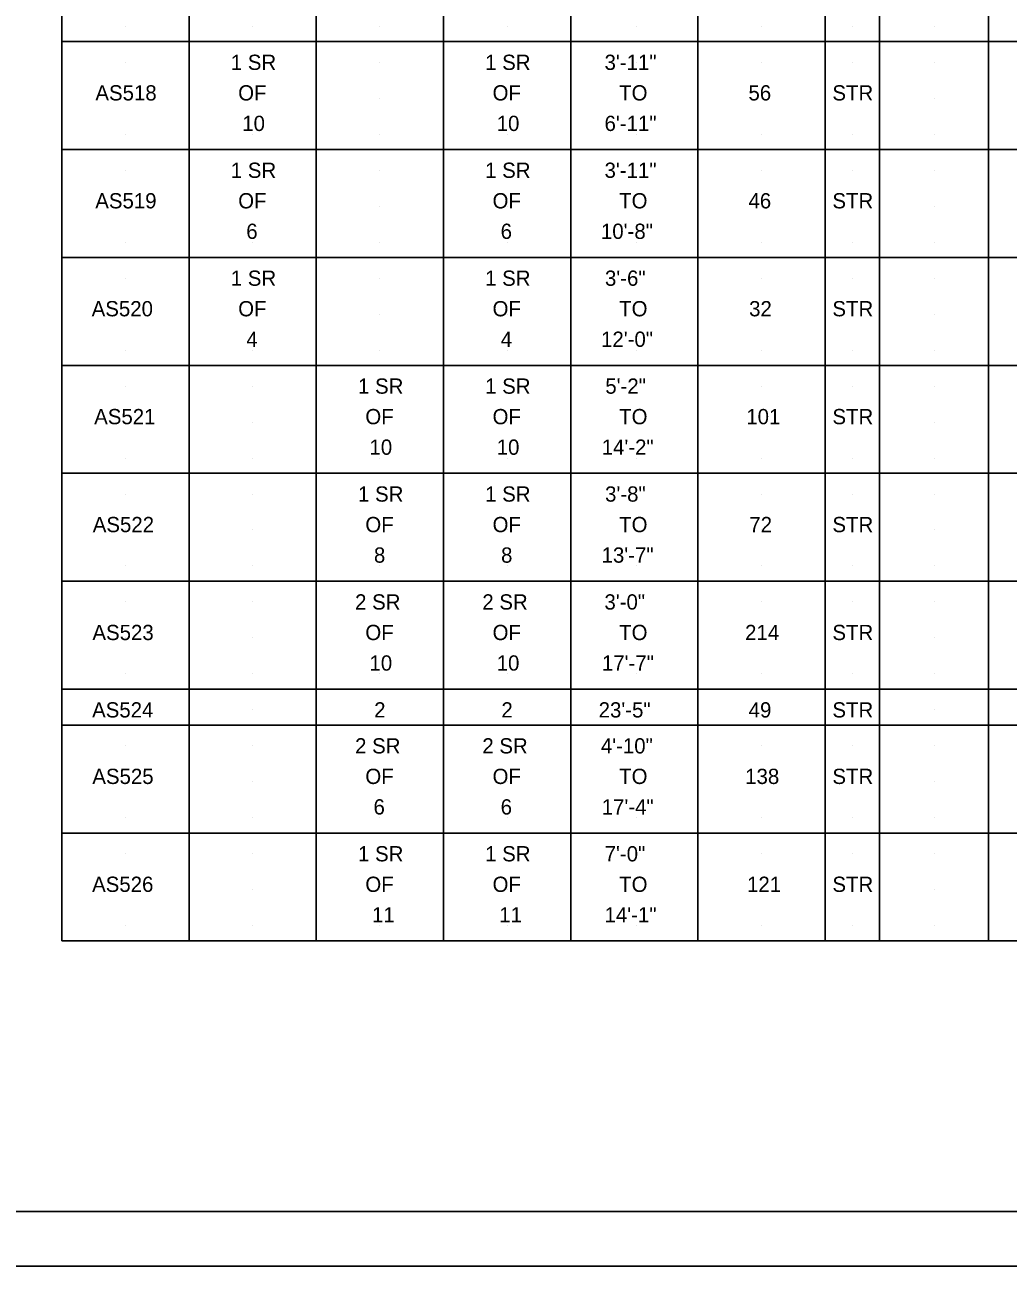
# Model space of a CAD drawing. Extents: x -31.1 to 2.9, y 8.5 to 31.4.
# Drawn here: x -15.02 to -6, y 8.48 to 19.87 of the extents above; entities that cross this region are included whole.
import ezdxf

# ---------------------------------------------------------------- set-up
doc = ezdxf.new("R2010")
doc.units = 0
for name, color, linetype in [('BR_P_Gen_Text', 7, 'Continuous'), ('Default', 7, 'Continuous'), ('SC_Scratch1', 7, 'Continuous')]:
    doc.layers.add(name, color=color, linetype=linetype)

msp = doc.modelspace()

# ---------------------------------------------------------------- linework, layer by layer
at = {"layer": 'BR_P_Gen_Text'}
for p, q in [((-13.511, 28.577), (-13.511, 11.467)), ((-12.345, 28.577), (-12.345, 11.467)), ((-11.178, 28.577), (-11.178, 11.467)), ((-10.011, 28.577), (-10.011, 11.467)), ((-8.845, 28.577), (-8.845, 11.467)), ((-7.678, 28.577), (-7.678, 11.467)), ((-7.178, 28.577), (-7.178, 11.467)), ((-6.178, 28.577), (-6.178, 11.467)), ((-14.678, 19.717), (-0.178, 19.717)), ((-14.678, 18.727), (-0.178, 18.727)), ((-14.678, 17.737), (-0.178, 17.737)), ((-14.678, 16.747), (-0.178, 16.747)), ((-14.678, 15.757), (-0.178, 15.757)), ((-14.678, 14.767), (-0.178, 14.767)), ((-14.678, 13.777), (-0.178, 13.777)), ((-14.678, 13.447), (-0.178, 13.447)), ((-14.678, 12.457), (-0.178, 12.457)), ((-0.178, 11.467), (-14.678, 11.467)), ((-14.678, 11.467), (-0.178, 11.467)), ((-14.678, 11.467), (-0.178, 11.467))]:
    msp.add_line(p, q, dxfattribs=at)
for points in [[(-31.128, 30.484), (2.872, 30.484), (2.872, 8.484), (-31.128, 8.484)], [(-29.128, 29.984), (1.372, 29.984), (1.372, 8.984), (-29.128, 8.984)]]:
    msp.add_lwpolyline(points, close=True, dxfattribs=at)
at = {"layer": 'Default'}
msp.add_line((-14.678, 29.627), (-14.678, 11.467), dxfattribs=at)
at = {"layer": 'SC_Scratch1'}
for p, q in [((-14.095, 19.857), (-14.095, 19.857)), ((-12.928, 19.857), (-12.928, 19.857)), ((-11.761, 19.857), (-11.761, 19.857)), ((-10.595, 19.857), (-10.595, 19.857)), ((-9.407, 19.857), (-9.407, 19.857)), ((-9.407, 19.857), (-9.407, 19.857)), ((-8.261, 19.857), (-8.261, 19.857)), ((-8.261, 19.857), (-8.261, 19.857)), ((-7.428, 19.857), (-7.428, 19.857)), ((-7.428, 19.857), (-7.428, 19.857)), ((-6.678, 19.857), (-6.678, 19.857)), ((-6.678, 19.857), (-6.678, 19.857)), ((-14.095, 19.527), (-14.095, 19.527)), ((-12.928, 19.527), (-12.928, 19.527)), ((-11.761, 19.527), (-11.761, 19.527)), ((-10.595, 19.527), (-10.595, 19.527)), ((-9.407, 19.527), (-9.407, 19.527)), ((-9.407, 19.527), (-9.407, 19.527)), ((-8.261, 19.527), (-8.261, 19.527)), ((-8.261, 19.527), (-8.261, 19.527)), ((-7.428, 19.527), (-7.428, 19.527)), ((-7.428, 19.527), (-7.428, 19.527)), ((-6.678, 19.527), (-6.678, 19.527)), ((-6.678, 19.527), (-6.678, 19.527)), ((-14.095, 19.197), (-14.095, 19.197)), ((-12.928, 19.197), (-12.928, 19.197)), ((-11.761, 19.197), (-11.761, 19.197)), ((-10.595, 19.197), (-10.595, 19.197)), ((-9.407, 19.197), (-9.407, 19.197)), ((-9.407, 19.197), (-9.407, 19.197)), ((-8.261, 19.197), (-8.261, 19.197)), ((-8.261, 19.197), (-8.261, 19.197)), ((-7.428, 19.197), (-7.428, 19.197)), ((-7.428, 19.197), (-7.428, 19.197)), ((-6.678, 19.197), (-6.678, 19.197)), ((-6.678, 19.197), (-6.678, 19.197)), ((-14.095, 18.867), (-14.095, 18.867)), ((-12.928, 18.867), (-12.928, 18.867)), ((-11.761, 18.867), (-11.761, 18.867)), ((-10.595, 18.867), (-10.595, 18.867)), ((-9.407, 18.867), (-9.407, 18.867)), ((-9.407, 18.867), (-9.407, 18.867)), ((-8.261, 18.867), (-8.261, 18.867)), ((-8.261, 18.867), (-8.261, 18.867)), ((-7.428, 18.867), (-7.428, 18.867)), ((-7.428, 18.867), (-7.428, 18.867)), ((-6.678, 18.867), (-6.678, 18.867)), ((-6.678, 18.867), (-6.678, 18.867)), ((-14.095, 18.537), (-14.095, 18.537)), ((-12.928, 18.537), (-12.928, 18.537)), ((-11.761, 18.537), (-11.761, 18.537)), ((-10.595, 18.537), (-10.595, 18.537)), ((-9.407, 18.537), (-9.407, 18.537)), ((-9.407, 18.537), (-9.407, 18.537)), ((-8.261, 18.537), (-8.261, 18.537)), ((-8.261, 18.537), (-8.261, 18.537)), ((-7.428, 18.537), (-7.428, 18.537)), ((-7.428, 18.537), (-7.428, 18.537)), ((-6.678, 18.537), (-6.678, 18.537)), ((-6.678, 18.537), (-6.678, 18.537)), ((-14.095, 18.207), (-14.095, 18.207)), ((-12.928, 18.207), (-12.928, 18.207)), ((-11.761, 18.207), (-11.761, 18.207)), ((-10.595, 18.207), (-10.595, 18.207)), ((-9.407, 18.207), (-9.407, 18.207)), ((-9.407, 18.207), (-9.407, 18.207)), ((-8.261, 18.207), (-8.261, 18.207)), ((-8.261, 18.207), (-8.261, 18.207)), ((-7.428, 18.207), (-7.428, 18.207)), ((-7.428, 18.207), (-7.428, 18.207)), ((-6.678, 18.207), (-6.678, 18.207)), ((-6.678, 18.207), (-6.678, 18.207)), ((-14.095, 17.877), (-14.095, 17.877)), ((-12.928, 17.877), (-12.928, 17.877)), ((-11.761, 17.877), (-11.761, 17.877)), ((-10.595, 17.877), (-10.595, 17.877)), ((-9.407, 17.877), (-9.407, 17.877)), ((-9.407, 17.877), (-9.407, 17.877)), ((-8.261, 17.877), (-8.261, 17.877)), ((-8.261, 17.877), (-8.261, 17.877)), ((-7.428, 17.877), (-7.428, 17.877)), ((-7.428, 17.877), (-7.428, 17.877)), ((-6.678, 17.877), (-6.678, 17.877)), ((-6.678, 17.877), (-6.678, 17.877)), ((-14.095, 17.547), (-14.095, 17.547)), ((-12.928, 17.547), (-12.928, 17.547)), ((-11.761, 17.547), (-11.761, 17.547)), ((-10.595, 17.547), (-10.595, 17.547)), ((-9.407, 17.547), (-9.407, 17.547)), ((-9.407, 17.547), (-9.407, 17.547)), ((-8.261, 17.547), (-8.261, 17.547)), ((-8.261, 17.547), (-8.261, 17.547)), ((-7.428, 17.547), (-7.428, 17.547)), ((-7.428, 17.547), (-7.428, 17.547)), ((-6.678, 17.547), (-6.678, 17.547)), ((-6.678, 17.547), (-6.678, 17.547)), ((-14.095, 17.217), (-14.095, 17.217)), ((-12.928, 17.217), (-12.928, 17.217)), ((-11.761, 17.217), (-11.761, 17.217)), ((-10.595, 17.217), (-10.595, 17.217)), ((-9.407, 17.217), (-9.407, 17.217)), ((-9.407, 17.217), (-9.407, 17.217)), ((-8.261, 17.217), (-8.261, 17.217)), ((-8.261, 17.217), (-8.261, 17.217)), ((-7.428, 17.217), (-7.428, 17.217)), ((-7.428, 17.217), (-7.428, 17.217)), ((-6.678, 17.217), (-6.678, 17.217)), ((-6.678, 17.217), (-6.678, 17.217)), ((-14.095, 16.887), (-14.095, 16.887)), ((-12.928, 16.887), (-12.928, 16.887)), ((-11.761, 16.887), (-11.761, 16.887)), ((-10.595, 16.887), (-10.595, 16.887)), ((-9.407, 16.887), (-9.407, 16.887)), ((-9.407, 16.887), (-9.407, 16.887)), ((-8.261, 16.887), (-8.261, 16.887)), ((-8.261, 16.887), (-8.261, 16.887)), ((-7.428, 16.887), (-7.428, 16.887)), ((-7.428, 16.887), (-7.428, 16.887)), ((-6.678, 16.887), (-6.678, 16.887)), ((-6.678, 16.887), (-6.678, 16.887)), ((-14.095, 16.557), (-14.095, 16.557)), ((-12.928, 16.557), (-12.928, 16.557)), ((-11.761, 16.557), (-11.761, 16.557)), ((-10.595, 16.557), (-10.595, 16.557)), ((-9.407, 16.557), (-9.407, 16.557)), ((-9.407, 16.557), (-9.407, 16.557)), ((-8.261, 16.557), (-8.261, 16.557)), ((-8.261, 16.557), (-8.261, 16.557)), ((-7.428, 16.557), (-7.428, 16.557)), ((-7.428, 16.557), (-7.428, 16.557)), ((-6.678, 16.557), (-6.678, 16.557)), ((-6.678, 16.557), (-6.678, 16.557)), ((-14.095, 16.227), (-14.095, 16.227)), ((-12.928, 16.227), (-12.928, 16.227)), ((-11.761, 16.227), (-11.761, 16.227)), ((-10.595, 16.227), (-10.595, 16.227)), ((-9.407, 16.227), (-9.407, 16.227)), ((-9.407, 16.227), (-9.407, 16.227)), ((-8.261, 16.227), (-8.261, 16.227)), ((-8.261, 16.227), (-8.261, 16.227)), ((-7.428, 16.227), (-7.428, 16.227)), ((-7.428, 16.227), (-7.428, 16.227)), ((-6.678, 16.227), (-6.678, 16.227)), ((-6.678, 16.227), (-6.678, 16.227)), ((-14.095, 15.897), (-14.095, 15.897)), ((-12.928, 15.897), (-12.928, 15.897)), ((-11.761, 15.897), (-11.761, 15.897)), ((-10.595, 15.897), (-10.595, 15.897)), ((-9.407, 15.897), (-9.407, 15.897)), ((-9.407, 15.897), (-9.407, 15.897)), ((-8.261, 15.897), (-8.261, 15.897)), ((-8.261, 15.897), (-8.261, 15.897)), ((-7.428, 15.897), (-7.428, 15.897)), ((-7.428, 15.897), (-7.428, 15.897)), ((-6.678, 15.897), (-6.678, 15.897)), ((-6.678, 15.897), (-6.678, 15.897)), ((-14.095, 15.567), (-14.095, 15.567)), ((-12.928, 15.567), (-12.928, 15.567)), ((-11.761, 15.567), (-11.761, 15.567)), ((-10.595, 15.567), (-10.595, 15.567)), ((-9.407, 15.567), (-9.407, 15.567)), ((-9.407, 15.567), (-9.407, 15.567)), ((-8.261, 15.567), (-8.261, 15.567)), ((-8.261, 15.567), (-8.261, 15.567)), ((-7.428, 15.567), (-7.428, 15.567)), ((-7.428, 15.567), (-7.428, 15.567)), ((-6.678, 15.567), (-6.678, 15.567)), ((-6.678, 15.567), (-6.678, 15.567)), ((-14.095, 15.237), (-14.095, 15.237)), ((-12.928, 15.237), (-12.928, 15.237)), ((-11.761, 15.237), (-11.761, 15.237)), ((-10.595, 15.237), (-10.595, 15.237)), ((-9.407, 15.237), (-9.407, 15.237)), ((-9.407, 15.237), (-9.407, 15.237)), ((-8.261, 15.237), (-8.261, 15.237)), ((-8.261, 15.237), (-8.261, 15.237)), ((-7.428, 15.237), (-7.428, 15.237)), ((-7.428, 15.237), (-7.428, 15.237)), ((-6.678, 15.237), (-6.678, 15.237)), ((-6.678, 15.237), (-6.678, 15.237)), ((-14.095, 14.907), (-14.095, 14.907)), ((-12.928, 14.907), (-12.928, 14.907)), ((-11.761, 14.907), (-11.761, 14.907)), ((-10.595, 14.907), (-10.595, 14.907)), ((-9.407, 14.907), (-9.407, 14.907)), ((-9.407, 14.907), (-9.407, 14.907)), ((-8.261, 14.907), (-8.261, 14.907)), ((-8.261, 14.907), (-8.261, 14.907)), ((-7.428, 14.907), (-7.428, 14.907)), ((-7.428, 14.907), (-7.428, 14.907)), ((-6.678, 14.907), (-6.678, 14.907)), ((-6.678, 14.907), (-6.678, 14.907)), ((-14.095, 14.577), (-14.095, 14.577)), ((-12.928, 14.577), (-12.928, 14.577)), ((-11.761, 14.577), (-11.761, 14.577)), ((-10.595, 14.577), (-10.595, 14.577)), ((-9.407, 14.577), (-9.407, 14.577)), ((-9.407, 14.577), (-9.407, 14.577)), ((-8.261, 14.577), (-8.261, 14.577)), ((-8.261, 14.577), (-8.261, 14.577)), ((-7.428, 14.577), (-7.428, 14.577)), ((-7.428, 14.577), (-7.428, 14.577)), ((-6.678, 14.577), (-6.678, 14.577)), ((-6.678, 14.577), (-6.678, 14.577)), ((-14.095, 14.247), (-14.095, 14.247)), ((-12.928, 14.247), (-12.928, 14.247)), ((-11.761, 14.247), (-11.761, 14.247)), ((-10.595, 14.247), (-10.595, 14.247)), ((-9.407, 14.247), (-9.407, 14.247)), ((-9.407, 14.247), (-9.407, 14.247)), ((-8.261, 14.247), (-8.261, 14.247)), ((-8.261, 14.247), (-8.261, 14.247)), ((-7.428, 14.247), (-7.428, 14.247)), ((-7.428, 14.247), (-7.428, 14.247)), ((-6.678, 14.247), (-6.678, 14.247)), ((-6.678, 14.247), (-6.678, 14.247)), ((-14.095, 13.917), (-14.095, 13.917)), ((-12.928, 13.917), (-12.928, 13.917)), ((-11.761, 13.917), (-11.761, 13.917)), ((-10.595, 13.917), (-10.595, 13.917)), ((-9.407, 13.917), (-9.407, 13.917)), ((-9.407, 13.917), (-9.407, 13.917)), ((-8.261, 13.917), (-8.261, 13.917)), ((-8.261, 13.917), (-8.261, 13.917)), ((-7.428, 13.917), (-7.428, 13.917)), ((-7.428, 13.917), (-7.428, 13.917)), ((-6.678, 13.917), (-6.678, 13.917)), ((-6.678, 13.917), (-6.678, 13.917)), ((-14.095, 13.587), (-14.095, 13.587)), ((-12.928, 13.587), (-12.928, 13.587)), ((-11.761, 13.587), (-11.761, 13.587)), ((-10.595, 13.587), (-10.595, 13.587)), ((-9.407, 13.587), (-9.407, 13.587)), ((-9.407, 13.587), (-9.407, 13.587)), ((-8.261, 13.587), (-8.261, 13.587)), ((-8.261, 13.587), (-8.261, 13.587)), ((-7.428, 13.587), (-7.428, 13.587)), ((-7.428, 13.587), (-7.428, 13.587)), ((-6.678, 13.587), (-6.678, 13.587)), ((-6.678, 13.587), (-6.678, 13.587)), ((-14.095, 13.257), (-14.095, 13.257)), ((-12.928, 13.257), (-12.928, 13.257)), ((-11.761, 13.257), (-11.761, 13.257)), ((-10.595, 13.257), (-10.595, 13.257)), ((-9.407, 13.257), (-9.407, 13.257)), ((-9.407, 13.257), (-9.407, 13.257)), ((-8.261, 13.257), (-8.261, 13.257)), ((-8.261, 13.257), (-8.261, 13.257)), ((-7.428, 13.257), (-7.428, 13.257)), ((-7.428, 13.257), (-7.428, 13.257)), ((-6.678, 13.257), (-6.678, 13.257)), ((-6.678, 13.257), (-6.678, 13.257)), ((-14.095, 12.927), (-14.095, 12.927)), ((-12.928, 12.927), (-12.928, 12.927)), ((-11.761, 12.927), (-11.761, 12.927)), ((-10.595, 12.927), (-10.595, 12.927)), ((-9.407, 12.927), (-9.407, 12.927)), ((-9.407, 12.927), (-9.407, 12.927)), ((-8.261, 12.927), (-8.261, 12.927)), ((-8.261, 12.927), (-8.261, 12.927)), ((-7.428, 12.927), (-7.428, 12.927)), ((-7.428, 12.927), (-7.428, 12.927)), ((-6.678, 12.927), (-6.678, 12.927)), ((-6.678, 12.927), (-6.678, 12.927)), ((-14.095, 12.597), (-14.095, 12.597)), ((-12.928, 12.597), (-12.928, 12.597)), ((-11.761, 12.597), (-11.761, 12.597)), ((-10.595, 12.597), (-10.595, 12.597)), ((-9.407, 12.597), (-9.407, 12.597)), ((-9.407, 12.597), (-9.407, 12.597)), ((-8.261, 12.597), (-8.261, 12.597)), ((-8.261, 12.597), (-8.261, 12.597)), ((-7.428, 12.597), (-7.428, 12.597)), ((-7.428, 12.597), (-7.428, 12.597)), ((-6.678, 12.597), (-6.678, 12.597)), ((-6.678, 12.597), (-6.678, 12.597)), ((-14.095, 12.267), (-14.095, 12.267)), ((-12.928, 12.267), (-12.928, 12.267)), ((-11.761, 12.267), (-11.761, 12.267)), ((-10.595, 12.267), (-10.595, 12.267)), ((-9.407, 12.267), (-9.407, 12.267)), ((-9.407, 12.267), (-9.407, 12.267)), ((-8.261, 12.267), (-8.261, 12.267)), ((-8.261, 12.267), (-8.261, 12.267)), ((-7.428, 12.267), (-7.428, 12.267)), ((-7.428, 12.267), (-7.428, 12.267)), ((-6.678, 12.267), (-6.678, 12.267)), ((-6.678, 12.267), (-6.678, 12.267)), ((-14.095, 11.937), (-14.095, 11.937)), ((-12.928, 11.937), (-12.928, 11.937)), ((-11.761, 11.937), (-11.761, 11.937)), ((-10.595, 11.937), (-10.595, 11.937)), ((-9.407, 11.937), (-9.407, 11.937)), ((-9.407, 11.937), (-9.407, 11.937)), ((-8.261, 11.937), (-8.261, 11.937)), ((-8.261, 11.937), (-8.261, 11.937)), ((-7.428, 11.937), (-7.428, 11.937)), ((-7.428, 11.937), (-7.428, 11.937)), ((-6.678, 11.937), (-6.678, 11.937)), ((-6.678, 11.937), (-6.678, 11.937)), ((-14.095, 11.607), (-14.095, 11.607)), ((-12.928, 11.607), (-12.928, 11.607)), ((-11.761, 11.607), (-11.761, 11.607)), ((-10.595, 11.607), (-10.595, 11.607)), ((-9.407, 11.607), (-9.407, 11.607)), ((-9.407, 11.607), (-9.407, 11.607)), ((-8.261, 11.607), (-8.261, 11.607)), ((-8.261, 11.607), (-8.261, 11.607)), ((-7.428, 11.607), (-7.428, 11.607)), ((-7.428, 11.607), (-7.428, 11.607)), ((-6.678, 11.607), (-6.678, 11.607)), ((-6.678, 11.607), (-6.678, 11.607))]:
    msp.add_line(p, q, dxfattribs=at)

# ---------------------------------------------------------------- texts
at = {"layer": 'BR_P_Gen_Text'}
for s, p in [('1 SR', (-13.129, 19.457)), ('1 SR', (-10.796, 19.457)), ('3\'-11"', (-9.701, 19.457)), ('AS518', (-14.371, 19.177)), ('OF', (-13.061, 19.177)), ('OF', (-10.728, 19.177)), ('TO', (-9.567, 19.177)), ('56', (-8.381, 19.177)), ('STR', (-7.611, 19.177)), ('10', (-13.024, 18.897)), ('10', (-10.69, 18.897)), ('6\'-11"', (-9.701, 18.897)), ('1 SR', (-13.129, 18.467)), ('1 SR', (-10.796, 18.467)), ('3\'-11"', (-9.701, 18.467)), ('AS519', (-14.372, 18.187)), ('OF', (-13.061, 18.187)), ('OF', (-10.728, 18.187)), ('TO', (-9.567, 18.187)), ('46', (-8.381, 18.187)), ('STR', (-7.611, 18.187)), ('6', (-12.987, 17.907)), ('6', (-10.654, 17.907)), ('10\'-8"', (-9.734, 17.907)), ('1 SR', (-13.129, 17.477)), ('1 SR', (-10.796, 17.477)), ('3\'-6"', (-9.697, 17.477)), ('AS520', (-14.405, 17.197)), ('OF', (-13.061, 17.197)), ('OF', (-10.728, 17.197)), ('TO', (-9.567, 17.197)), ('32', (-8.375, 17.197)), ('STR', (-7.611, 17.197)), ('4', (-12.986, 16.917)), ('4', (-10.653, 16.917)), ('12\'-0"', (-9.733, 16.917)), ('1 SR', (-11.962, 16.487)), ('1 SR', (-10.796, 16.487)), ('5\'-2"', (-9.694, 16.487)), ('AS521', (-14.382, 16.207)), ('OF', (-11.895, 16.207)), ('OF', (-10.728, 16.207)), ('TO', (-9.567, 16.207)), ('101', (-8.401, 16.207)), ('STR', (-7.611, 16.207)), ('10', (-11.857, 15.927)), ('10', (-10.69, 15.927)), ('14\'-2"', (-9.727, 15.927)), ('1 SR', (-11.962, 15.497)), ('1 SR', (-10.796, 15.497)), ('3\'-8"', (-9.696, 15.497)), ('AS522', (-14.395, 15.217)), ('OF', (-11.895, 15.217)), ('OF', (-10.728, 15.217)), ('TO', (-9.567, 15.217)), ('72', (-8.373, 15.217)), ('STR', (-7.611, 15.217)), ('8', (-11.816, 14.937)), ('8', (-10.65, 14.937)), ('13\'-7"', (-9.728, 14.937)), ('2 SR', (-11.989, 14.507)), ('2 SR', (-10.822, 14.507)), ('3\'-0"', (-9.702, 14.507)), ('AS523', (-14.398, 14.227)), ('OF', (-11.895, 14.227)), ('OF', (-10.728, 14.227)), ('TO', (-9.567, 14.227)), ('214', (-8.412, 14.227)), ('STR', (-7.611, 14.227)), ('10', (-11.857, 13.947)), ('10', (-10.69, 13.947)), ('17\'-7"', (-9.725, 13.947)), ('AS524', (-14.401, 13.517)), ('2', (-11.814, 13.517)), ('2', (-10.647, 13.517)), ('23\'-5"', (-9.755, 13.517)), ('49', (-8.379, 13.517)), ('STR', (-7.611, 13.517)), ('2 SR', (-11.989, 13.187)), ('2 SR', (-10.822, 13.187)), ('4\'-10"', (-9.735, 13.187)), ('AS525', (-14.399, 12.907)), ('OF', (-11.895, 12.907)), ('OF', (-10.728, 12.907)), ('TO', (-9.567, 12.907)), ('138', (-8.411, 12.907)), ('STR', (-7.611, 12.907)), ('6', (-11.82, 12.627)), ('6', (-10.654, 12.627)), ('17\'-4"', (-9.727, 12.627)), ('1 SR', (-11.962, 12.197)), ('1 SR', (-10.796, 12.197)), ('7\'-0"', (-9.7, 12.197)), ('AS526', (-14.401, 11.917)), ('OF', (-11.895, 11.917)), ('OF', (-10.728, 11.917)), ('TO', (-9.567, 11.917)), ('121', (-8.394, 11.917)), ('STR', (-7.611, 11.917)), ('11', (-11.834, 11.637)), ('11', (-10.667, 11.637)), ('14\'-1"', (-9.701, 11.637))]:
    msp.add_text(s, height=0.14, dxfattribs=at).set_placement(p)

doc.saveas('drawing.dxf')
